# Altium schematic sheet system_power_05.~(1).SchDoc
size 431 x 279 mm; Date: Not shown in title block; ApprovedBy: Not shown in title block; CheckedBy: Not shown in title block; Author: Not shown in title block; CompanyName: Not shown in title block; Engineer: Not shown in title block; Organization: Not shown in title block; Address1: Not shown in title block; Address2: Not shown in title block; Address3: Not shown in title block; Address4: Not shown in title block; DocumentNumber: 38; Revision: Use project parameter SCH_Rev; SheetNumber: 38; SheetTotal: 38; PageSetup: Record=PageOptions¦CenterHorizontal=True¦CenterVertical=True¦PrintScale=1.00¦XCorrection=1.00¦YCorrection=1.00¦PrintKind=0¦BorderSize=5000000¦LeftOffset=0¦BottomOffset=0¦Orientation=2¦PaperLength=1000¦PaperWidth=1000¦Scale=100¦PaperSource=15¦PrintQuality=600¦MediaType=1¦DitherType=10¦PaperKind=Letter¦PrintScaleMode=1
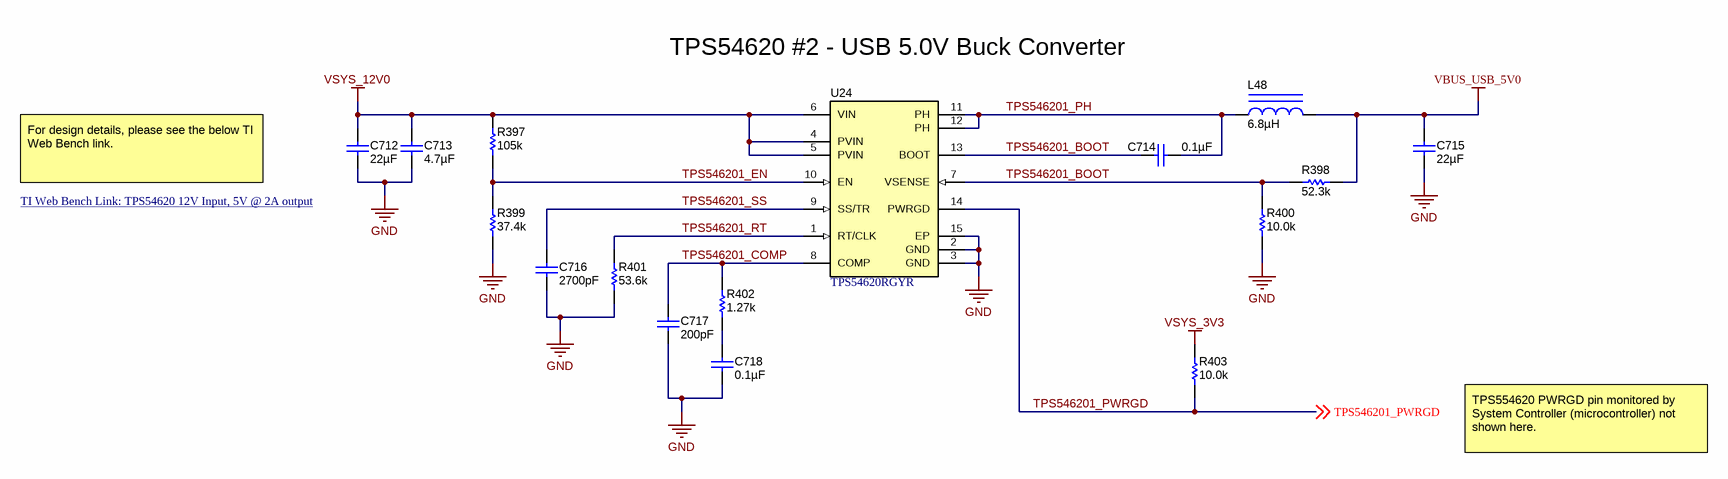
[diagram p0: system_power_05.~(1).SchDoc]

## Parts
C712  ValueDisplayed: 22µF  [1210_270]  (hidden comment: GRM32ER61E226KE15L)
C713  ValueDisplayed: 4.7µF  [0805_HV]  (hidden comment: GRM21BR61E475KA12L)
C714  ValueDisplayed: 0.1µF  [0805_HV]  (hidden comment: 08053C104KAT2A)
C715  ValueDisplayed: 22µF  [1210_270]  (hidden comment: GRM32ER61E226KE15L)
C716  ValueDisplayed: 2700pF  [0805_HV]  (hidden comment: CC0805KRX7R9BB272)
C717  ValueDisplayed: 200pF  [0402]  (hidden comment: GRM1555C1H201JA01D)
C718  ValueDisplayed: 0.1µF  [0805_HV]  (hidden comment: GRM21BR71E104KA01L)
L48  ValueDisplayed: 6.8µH  [SRN6045]  (hidden comment: SRN6045-6R8Y)
R397  ValueDisplayed: 105k  [0402]  (hidden comment: CRCW0402105KFKED)
R398  ValueDisplayed: 52.3k  [0402]  (hidden comment: CRCW040252K3FKED)
R399  ValueDisplayed: 37.4k  [0402]  (hidden comment: CRCW040237K4FKED)
R400  ValueDisplayed: 10.0k  [0402]  (hidden comment: CRCW040210K0DHEDP)
R401  ValueDisplayed: 53.6k  [0402]  (hidden comment: CRCW040253K6FKED)
R402  ValueDisplayed: 1.27k  [0402]  (hidden comment: CRCW04021K27FKED)
R403  ValueDisplayed: 10.0k  [0402]  (hidden comment: CRCW040210K0DHEDP)
U24  TPS54620RGYR  [RHL0014A]

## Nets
GND: C712.2 C713.2 C715.2 C716.2 C717.2 C718.2 R399.1 R400.1 R401.1 U24.2(GND) U24.3(GND) U24.15(EP)
VBUS_USB_5V0: C715.1 L48.2 R398.2
VSYS_3V3: R403.2
VSYS_12V0: C712.1 C713.1 R397.2 U24.4(PVIN) U24.5(PVIN) U24.6(VIN)
TPS546201_BOOT: C714.2 R398.1 R400.2 U24.7(VSENSE) U24.13(BOOT)
TPS546201_COMP: C717.1 R402.2 U24.8(COMP)
TPS546201_EN: R397.1 R399.2 U24.10(EN)
TPS546201_PH: C714.1 L48.1 U24.11(PH) U24.12(PH)
TPS546201_PWRGD: R403.1 U24.14(PWRGD) ; off-sheet TPS546201_PWRGD
TPS546201_RT: R401.2 U24.1(RT/CLK)
TPS546201_SS: C716.1 U24.9(SS/TR)
NetC718_1: C718.1 R402.1

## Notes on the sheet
- TPS54620 #2 - USB 5.0V Buck Converter
- For design details, please see the below TI Web Bench link.
- (near C712) TI Web Bench Link: TPS54620 12V Input, 5V @ 2A output <https://webench.ti.com/appinfo/webench/scripts/SDP.cgi?ID=9C7178BC14FEBCDB>
- TPS554620 PWRGD pin monitored by System Controller (microcontroller) not shown here.

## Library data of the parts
C712 C715 = GRM32ER61E226KE15L: CAP, CERM, 22 µF, 25 V, +/- 10%, X5R, 1210; Manufacturer: MuRata; Polarized: N; CompType: Capacitor; Value: 22uF; U/M: EA; Cap_F: 0.000022; Tolerance_%: 10; ESR_ohm: 0.002; Value1: 0.002 ohm; VDC_V: 25; Value2: 25V; IRMS_A: 3.67; TaMin_C: -55; TaMax_C: 85; Cap_Case: 1210; SizeArea_mm2: 8; SizeAreaWB_mm2: 14.7; SizeX_mm: 3.2; SizeY_mm: 2.5; SizeZ_mm: 2.7; AEC Category: Q200
C713 = GRM21BR61E475KA12L: CAP, CERM, 4.7 µF, 25 V, +/- 10%, X5R, 0805; Manufacturer: MuRata; Polarized: N; CompType: Capacitor; Value: 4.7uF; U/M: EA; Cap_F: 0.0000047; Tolerance_%: 10; ESR_ohm: 0.004; Value1: 0.004 ohm; VDC_V: 25; Value2: 25V; TaMin_C: -55; TaMax_C: 85; Cap_Case: 0805; SizeArea_mm2: 2.5; SizeAreaWB_mm2: 6.75; SizeX_mm: 2; SizeY_mm: 1.25; SizeZ_mm: 1.45; AEC Category: Q200
C714 = 08053C104KAT2A: CAP, CERM, 0.1 µF, 25 V, +/- 10%, X7R, 0805; Manufacturer: AVX; Polarized: N; CompType: Capacitor; Value: 0.1uF; U/M: EA; Cap_F: 0.0000001; Tolerance_%: 10; ESR_ohm: 0.28; Value1: 0.28 ohm; VDC_V: 25; Value2: 25V; TaMin_C: -55; TaMax_C: 125; Cap_Case: 0805; SizeArea_mm2: 2.5; SizeAreaWB_mm2: 6.75; SizeX_mm: 2; SizeY_mm: 1.25; SizeZ_mm: 1.45; AEC Category: Q200
C716 = CC0805KRX7R9BB272: CAP, CERM, 2700 pF, 50 V, +/- 10%, X7R, 0805; Manufacturer: Yageo America; Polarized: N; CompType: Capacitor; Value: 2700pF; U/M: EA; Cap_F: 0.0000000027; Tolerance_%: 10; Value1: Unknown; VDC_V: 50; Value2: 50V; TaMin_C: -55; TaMax_C: 125; Cap_Case: 0805; SizeArea_mm2: 2.5; SizeAreaWB_mm2: 6.75; SizeX_mm: 2; SizeY_mm: 1.25; SizeZ_mm: 1.45; AEC Category: Q200
C717 = GRM1555C1H201JA01D: CAP, CERM, 200 pF, 50 V, +/- 5%, C0G/NP0, 0402; Manufacturer: MuRata; Polarized: N; CompType: Capacitor; Value: 200pF; U/M: EA; Cap_F: 0.0000000002; Tolerance_%: 5; Value1: Unknown; VDC_V: 50; Value2: 50V; TaMin_C: -55; TaMax_C: 125; SizeArea_mm2: 0.5; SizeAreaWB_mm2: 3; SizeX_mm: 1; SizeZ_mm: 0.6; AEC Category: Q200
C718 = GRM21BR71E104KA01L: CAP, CERM, 0.1 µF, 25 V, +/- 10%, X7R, 0805; Manufacturer: MuRata; Polarized: N; CompType: Capacitor; Value: 0.1uF; U/M: EA; Cap_F: 0.0000001; Tolerance_%: 10; Value1: Unknown; VDC_V: 25; Value2: 25V; TaMin_C: -55; TaMax_C: 125; Cap_Case: 0805; SizeArea_mm2: 2.5; SizeAreaWB_mm2: 6.75; SizeX_mm: 2; SizeY_mm: 1.25; SizeZ_mm: 1.45; AEC Category: Q200
L48 = SRN6045-6R8Y: Inductor, Drum Core, Ferrite, 6.8 µH, 2.8 A, 0.0473 ohm, SMD; Manufacturer: Bourns; Value: 6.8uH; Ind_H: 6.8E-6; Imax_A: 2.8; Irms: 2.8A @ 40C rise; Isat: 3.8A @ 30% inductance drop; DCR_ohm: 0.0473; Value2: 2.8A; AEC Category: Q200
R397 = CRCW0402105KFKED: RES, 105 k, 1%, 0.063 W, 0402; Manufacturer: Vishay-Dale; CompType: Resistor; Value: 105k; Res_ohm: 105000; Tolerance_%: 1; Power_W: 0.063; Value2: 0.063W; VDC_V: 50; TempCo: 100 ppm/C; SizeArea_mm2: 0.5; SizeZ_mm: 0.6; EIA_Code: E96; U/M: EA; AEC Category: Q200
R398 = CRCW040252K3FKED: RES, 52.3 k, 1%, 0.063 W, 0402; Manufacturer: Vishay-Dale; CompType: Resistor; Value: 52.3k; Res_ohm: 52300; Value_Code: 52k3; Tolerance_%: 1; Power_W: 0.063; Value2: 0.063W; VDC_V: 50; TempCo: 100 ppm/C; SizeArea_mm2: 0.5; SizeZ_mm: 0.6; EIA_Code: E96; U/M: EA; AEC Category: Q200
R399 = CRCW040237K4FKED: RES, 37.4 k, 1%, 0.063 W, 0402; Manufacturer: Vishay-Dale; CompType: Resistor; Value: 37.4k; Res_ohm: 37400; Value_Code: 37k4; Tolerance_%: 1; Power_W: 0.063; Value2: 0.063W; VDC_V: 50; TempCo: 100 ppm/C; SizeArea_mm2: 0.5; SizeZ_mm: 0.6; EIA_Code: E96; U/M: EA; AEC Category: Q200
R400 R403 = CRCW040210K0DHEDP: RES, 10.0 k, 0.5%, 0.063 W, 0402; Manufacturer: Vishay-Dale; CompType: Resistor; Value: 10.0k; Res_ohm: 10000; Value_Code: 10k0; Tolerance_%: 0.5; Power_W: 0.063; Value2: 0.063W; VDC_V: 50; TempCo: 50 ppm/C; SizeX_mm: 1; SizeZ_mm: 0.6; EIA_Code: E192; U/M: EA; AEC Category: Q200
R401 = CRCW040253K6FKED: RES, 53.6 k, 1%, 0.063 W, 0402; Manufacturer: Vishay-Dale; CompType: Resistor; Value: 53.6k; Res_ohm: 53600; Value_Code: 53k6; Tolerance_%: 1; Power_W: 0.063; Value2: 0.063W; VDC_V: 50; TempCo: 100 ppm/C; SizeArea_mm2: 0.5; SizeZ_mm: 0.6; EIA_Code: E96; U/M: EA; AEC Category: Q200
R402 = CRCW04021K27FKED: RES, 1.27 k, 1%, 0.063 W, 0402; Manufacturer: Vishay-Dale; CompType: Resistor; Value: 1.27k; Res_ohm: 1270; Value_Code: 1k27; Tolerance_%: 1; Power_W: 0.063; Value2: 0.063W; VDC_V: 50; TempCo: 100 ppm/C; SizeArea_mm2: 0.5; SizeZ_mm: 0.6; EIA_Code: E96; U/M: EA; AEC Category: Q200
U24 = TPS54620RGYR: Buck Step Down Regulator with 4.5 to 17 V Input and 0.8 to 15 V Output, -40 to 150 degC, 14-Pin VQFN (RGY), Green (RoHS & no Sb/Br); Manufacturer: Texas Instruments; Alternate PartNumber: Equivalent; Duty Cycle(Max)(%): 98; Iout(Max)(A): 6; Iq(Typ)(mA): 0.6; Rating: Catalog; Regulated Outputs(#): 1; SubFamily: Step-Down Regulator; Switch Current Limit(Typ)(A): 8; Synchronous Rectification: TRUE; Vin(Max)(V): 17; Vin(Min)(V): 4.5; Vout(Max)(V): 15; Vout(Min)(V): 0.8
